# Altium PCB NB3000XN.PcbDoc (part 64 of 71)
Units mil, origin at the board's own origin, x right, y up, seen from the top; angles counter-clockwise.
Board outline 9527.56 x 6929.77 mil, 6 copper layers (Top Layer, GND+SHIELD, MidLayer1, MidLayer2, P2 - 3V3+5V0, Bottom Layer), stack 62.375 mil thick; 832 components, 1027 nets, 4655 pads, 4981 vias.
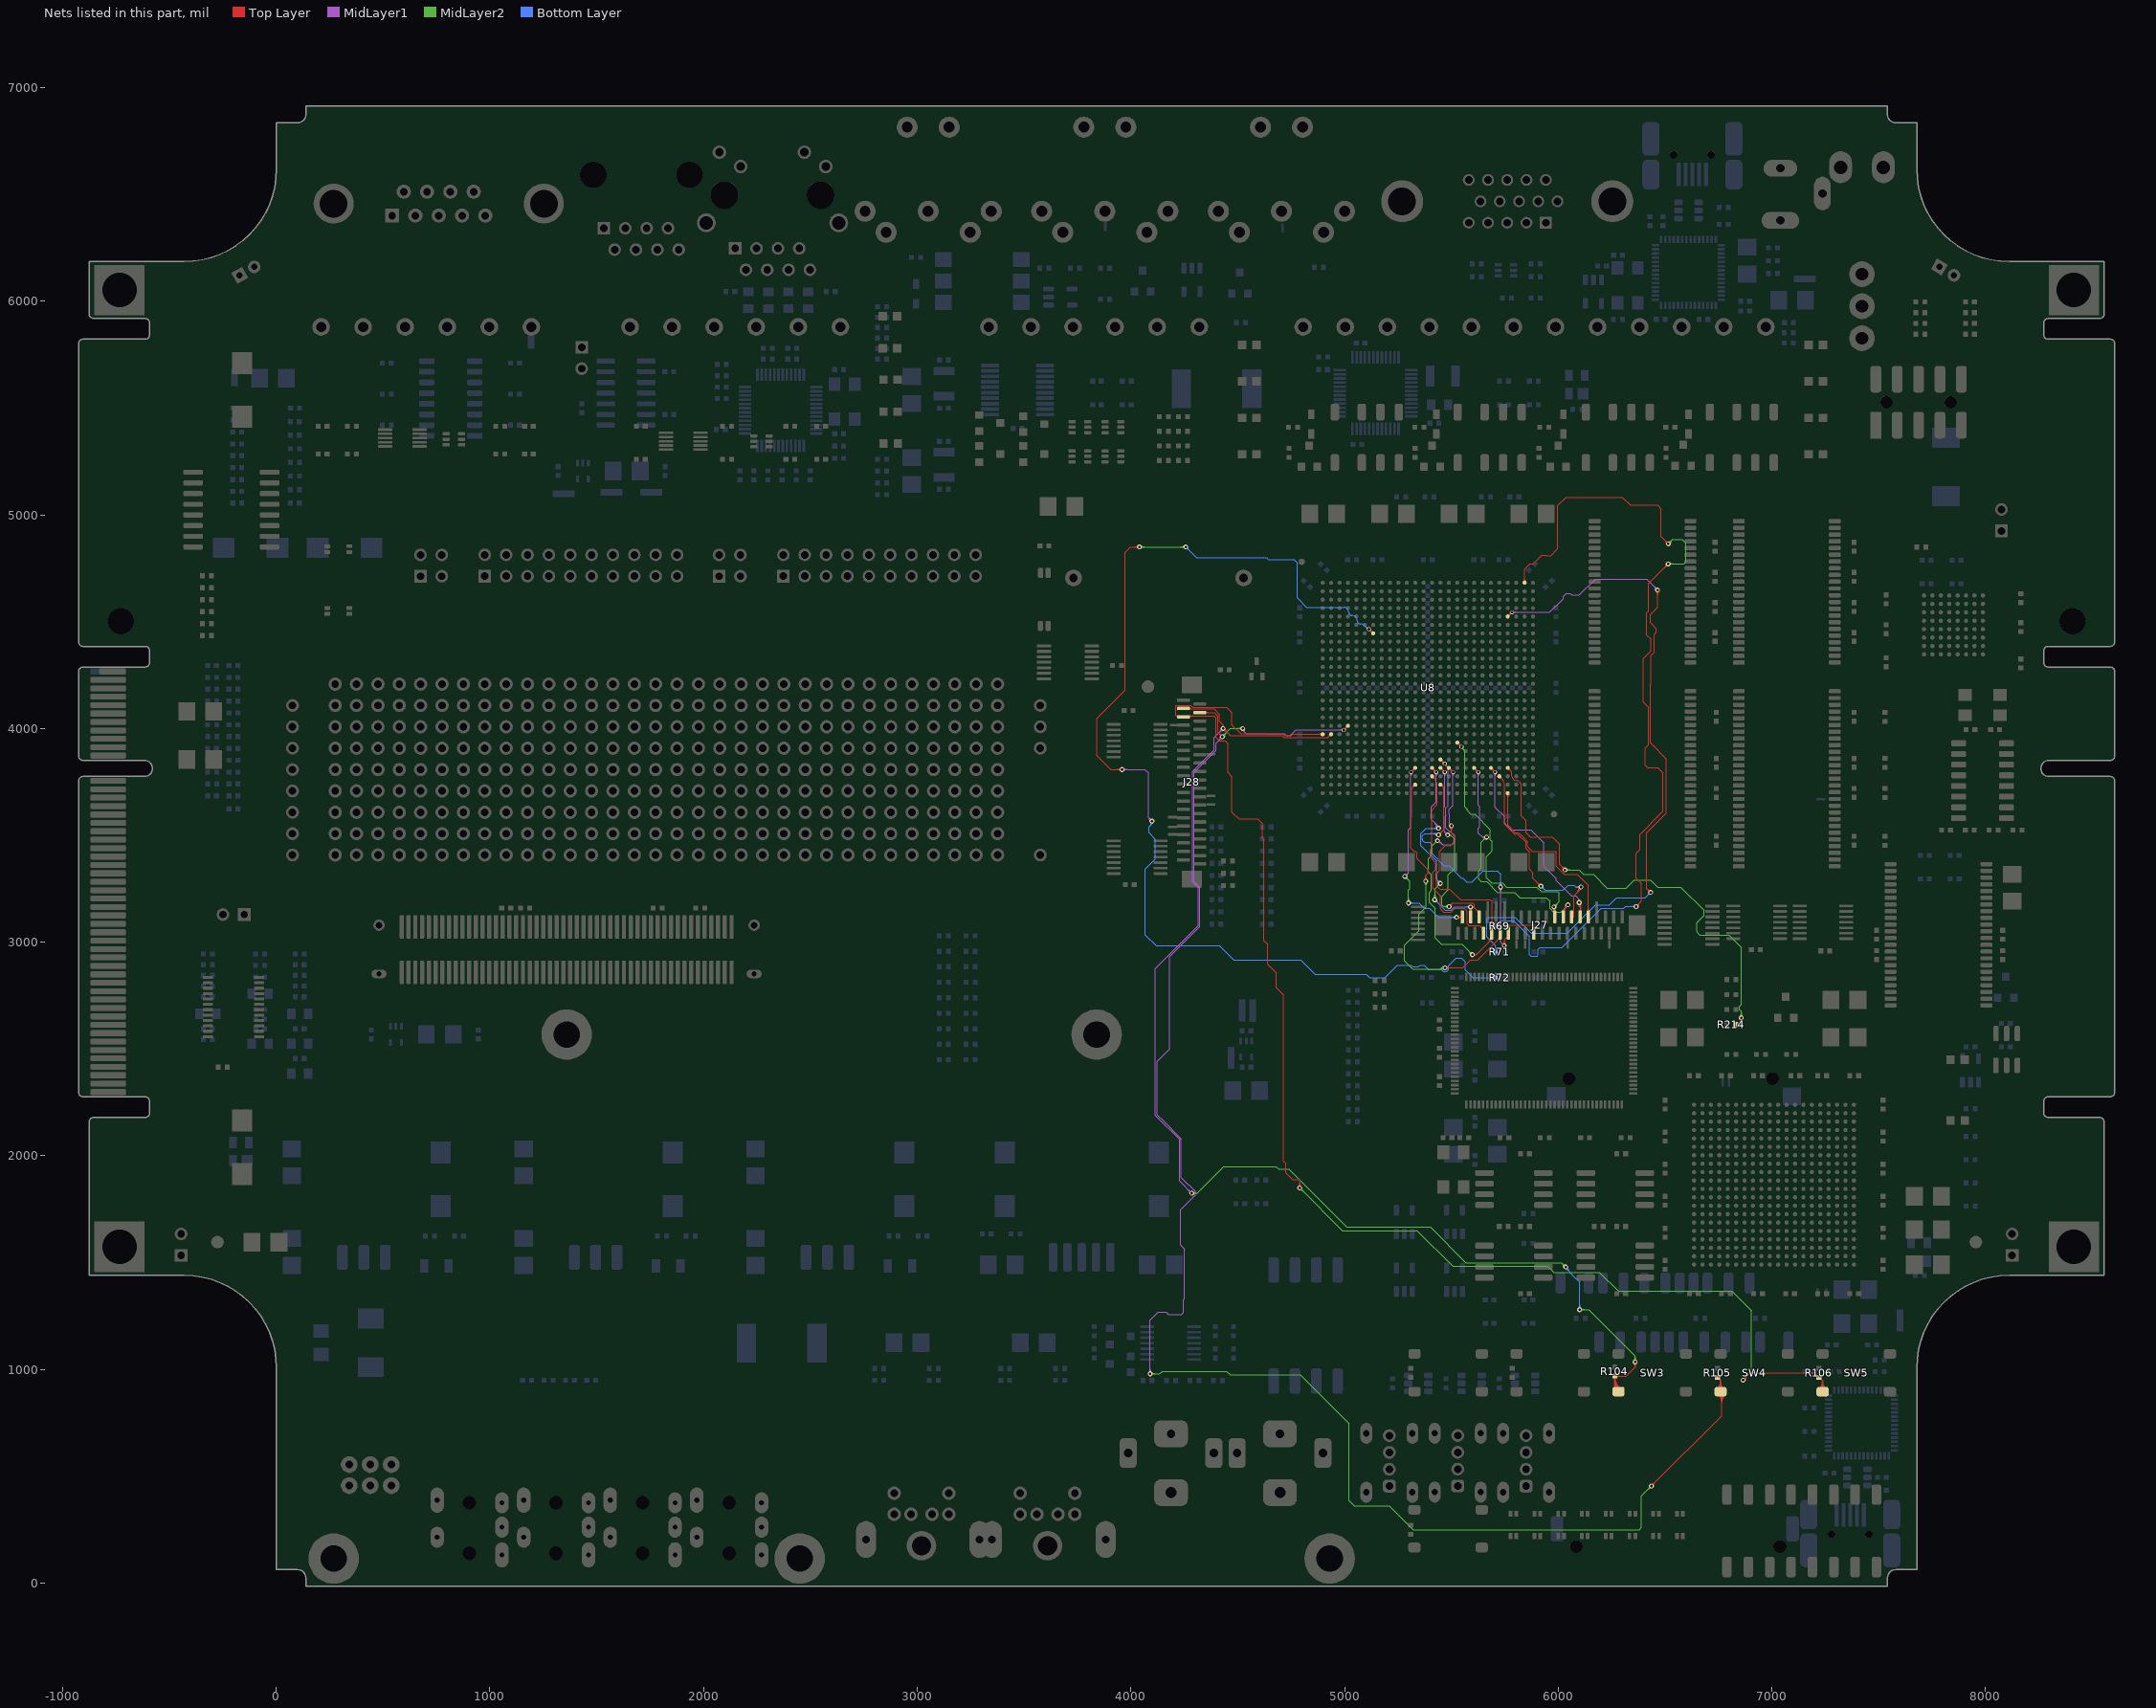
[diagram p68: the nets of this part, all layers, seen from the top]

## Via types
v1: diameter 23, hole 11.81, Top Layer to Bottom Layer, 3672 vias
v2: diameter 26, hole 11.81, Top Layer to Bottom Layer, 461 vias
v3: diameter 19, hole 11.81, Top Layer to Bottom Layer, tented both sides, 396 vias
v4: diameter 23.62, hole 11.81, Top Layer to Bottom Layer, 288 vias
v5: diameter 20, hole 11.81, Top Layer to Bottom Layer, 91 vias
v6: diameter 23, hole 11.81, Top Layer to Bottom Layer, tented both sides, 50 vias
v7: diameter 31, hole 11.81, Top Layer to Bottom Layer, 15 vias
v8: diameter 27.56, hole 11.81, Top Layer to Bottom Layer, tented both sides, 4 vias
v9: diameter 29, hole 11.81, Top Layer to Bottom Layer, 3 vias
v10: diameter 21, hole 11.81, Top Layer to Bottom Layer, 1 vias

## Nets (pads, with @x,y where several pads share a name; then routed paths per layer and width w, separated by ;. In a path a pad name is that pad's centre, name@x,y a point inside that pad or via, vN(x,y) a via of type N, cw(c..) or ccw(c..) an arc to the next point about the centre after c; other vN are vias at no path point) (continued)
SW#.D2: J28.3 R104.1 SW3.2 U8.W2 | length 7158.2
  Top Layer w4: J28.3@4246.61,4094.49 4248.52,4094.49 4251.3,4091.71 4390.19,4091.71 4415.19,4066.71 4415.19,4033.37 4431.86,4016.71 ; J28.3@4270.07,4095.81 ccw(c4279.98,4105.72) 4279.98,4091.71 ; J28.3@4272.89,4090.33 cw(c4276.21,4087.02) J28.3@4276.21,4091.71 ; J28.3@4272.89,4098.64 ccw(c4289.63,4115.38) 4289.63,4091.71 ; v1@4427.02,4008.22 ccw(c4421.99,4016.71) 4431.86,4016.71 ; v1@4431.86,3990.54 cw(c4431.86,3967.61) 4448.07,3983.82 cw(c4464.29,4000.04) v1@4441.36,4000.04 ; v1@4431.86,3994.54 cw(c4431.86,3981.26) 4441.25,3990.65 cw(c4450.64,4000.04) v1@4437.36,4000.04 ; v1@4436.7,4008.22 cw(c4441.73,4016.71) 4431.86,4016.71 ; U8.W2@4929.9,3973.46 cw(c4912.17,3973.46) 4924.71,3960.93 ; U8.W2@4937.24,3966.12 ccw(c4937.24,3948.4) 4924.71,3960.93 ; R104.1@6258.41,962.23 cw(c6242.5,946.32) 6265,946.32 cw(c6287.5,946.32) R104.1@6271.59,962.23 ; R104.1@6261.24,965.06 cw(c6252.16,955.98) 6265,955.98 cw(c6277.84,955.98) R104.1@6268.76,965.06 ; SW3.2@6262.02,911.31 ccw(c6254.84,918.49) SW3.2@6265,918.49 ; 6265,923.84 ccw(c6300.9,923.84) SW3.2@6276.85,897.18 ; 6265,932.83 ccw(c6309.01,932.83) SW3.2@6279.53,900.15 ; 6265,941.83 ccw(c6317.13,941.83) SW3.2@6282.21,903.12 ; 6265,950.82 ccw(c6325.24,950.82) SW3.2@6284.89,906.09 ; R104.1@6265,959.82 ccw(c6333.35,959.82) SW3.2@6287.57,909.06 ; R104.1@6269.25,965.06 cw(c6278.33,955.98) 6278.33,968.82 cw(c6278.33,981.66) R104.1@6269.25,972.58 ; R104.1@6272.08,962.23 cw(c6287.99,946.32) 6287.99,968.82 cw(c6287.99,991.32) R104.1@6272.08,975.41 ; SW3.2@6282.52,896.81 6265,914.33 R104.1@6265,968.82 ; SW3.2@6290.25,912.03 cw(c6341.47,968.81) R104.1@6265,968.82 ; v1@6353.19,1028.28 cw(c6336.97,1012.06) 6359.9,1012.06 cw(c6382.84,1012.06) v1@6366.62,1028.28 ; v1@6356.01,1031.11 cw(c6346.62,1021.72) 6359.9,1021.72 cw(c6373.18,1021.72) v1@6363.79,1031.11 ; v1(6359.9,1035) 6359.9,1010.93 6317.79,968.82 R104.1@6265,968.82 ; 4431.86,4016.71 v1(4431.86,4000.04) 4465.19,3966.71 4708.29,3966.71 4717.04,3957.96 ; 4717.04,3957.96 4796,3957.96 ; 4717.04,3957.96 4780,3957.96 4796,3957.96 ; 4796,3957.96 4855.26,3957.96 4860,3957.96 4870,3957.96 4917.53,3957.96 ccw(c4917.53,3968.11) 4924.71,3960.93
  MidLayer1 w4: v1@4275.5,1825 ccw(c4252.56,1825) 4268.78,1841.22 ccw(c4285,1857.43) v1@4285,1834.5 ; v1@4279.5,1825 ccw(c4266.22,1825) 4275.61,1834.39 ccw(c4285,1843.78) v1@4285,1830.5 ; v1(4285,1825) 4228,1882 4228,2076.69 4115.19,2189.5 4115.19,2877.67 4315.19,3077.67 4315.19,3255 4288.52,3281.67 4288.52,3798.71 4390.19,3900.37 4390.19,3958.37 v1(4431.86,4000.04) ; v1@4422.36,4000.04 cw(c4399.42,4000.04) 4415.64,3983.82 cw(c4431.86,3967.61) v1@4431.86,3990.54 ; v1@4426.36,4000.04 cw(c4413.08,4000.04) 4422.47,3990.65 cw(c4431.86,3981.26) v1@4431.86,3994.54
  MidLayer2 w4: v1@4285,1827.15 v1(4285,1825) 4310,1825 4435.04,1950.04 4678.29,1950.04 4691.15,1937.19 4739.36,1937.19 5009.84,1666.71 5401.5,1666.71 5568.17,1500.04 6014.96,1500.04 v4(6035,1480) ; v1@4288.89,1821.11 cw(c4298.28,1811.72) 4298.28,1825 cw(c4298.28,1838.28) v1@4288.89,1828.89 ; v1@4291.72,1818.28 cw(c4307.93,1802.06) 4307.93,1825 cw(c4307.93,1847.93) v1@4291.72,1831.72 ; v4@6025.19,1480 ccw(c6001.5,1480) 6018.25,1496.75 ccw(c6035,1513.5) v4@6035,1489.81 ; v4@6029.19,1480 ccw(c6015.16,1480) 6025.08,1489.92 ccw(c6035,1499.84) v4@6035,1485.81 ; v4(6100,1280) 6143.56,1280 6359.9,1063.66 v1(6359.9,1035) ; v4@6104.11,1275.89 cw(c6114.03,1265.97) 6114.03,1280 cw(c6114.03,1294.03) v4@6104.11,1284.11 ; v4@6106.94,1273.06 cw(c6123.69,1256.31) 6123.69,1280 cw(c6123.69,1303.69) v4@6106.94,1286.94 ; v1@6353.19,1041.72 ccw(c6336.97,1057.93) 6359.9,1057.93 ccw(c6382.84,1057.93) v1@6366.62,1041.72 ; v1@6356.01,1038.89 ccw(c6346.62,1048.28) 6359.9,1048.28 ccw(c6373.18,1048.28) v1@6363.79,1038.89
  Bottom Layer w4: v4@6035,1470.19 cw(c6035,1458.57) 6043.21,1466.79 ; v4(6035,1480) 6040,1480 6040,1470 6070,1440 ; v4@6036.81,1480 ccw(c6053.25,1480) 6041.63,1468.37 ; v4@6040.81,1480 ccw(c6066.91,1480) 6048.46,1461.54 ; v4@6044.81,1480 ccw(c6080.57,1480) 6055.28,1454.72 ; 6055,1455 6070,1440 ; v4@6093.06,1286.94 ccw(c6076.31,1303.69) 6100,1303.69 ccw(c6123.69,1303.69) v4@6106.94,1286.94 ; v4@6095.89,1284.11 ccw(c6085.97,1294.03) 6100,1294.03 ccw(c6114.03,1294.03) v4@6104.11,1284.11 ; v4(6100,1280) 6100,1410 6070,1440
SW#.D3: J28.4 R105.2 SW4.2 U8.V4 | length 9059.8
  Top Layer w4: J28.4@4331.86,4074.8 J28.4@4323.39,4074.8 4389.09,4074.8 4406.86,4057.04 4406.86,3983.37 v1(4428.52,3961.71) ; J28.4@4349.67,4070.65 cw(c4359.69,4060.62) 4359.69,4074.8 cw(c4359.69,4088.98) J28.4@4349.67,4078.96 ; v1@4419.02,3961.71 ccw(c4396.09,3961.71) 4412.31,3977.93 ccw(c4428.52,3994.14) v1@4428.52,3971.21 ; v1@4423.02,3961.71 ccw(c4409.75,3961.71) 4419.14,3971.1 ccw(c4428.52,3980.49) v1@4428.52,3967.21 ; v3(4996.3,3993.15) U8.V4@5015.98,4012.83 ; v3@5003.8,3993.15 cw(c5021.91,3993.15) 5009.1,4005.95 ; v3@5003.8,3993.15 cw(c5021.91,3993.15) 5009.1,4005.95 ; U8.V4@5008.48,4012.83 cw(c4990.38,4012.83) 5003.18,4000.03 cw(c5015.98,3987.23) U8.V4@5015.98,4005.33 ; U8.V4@5008.64,4012.83 cw(c4990.92,4012.83) 5003.45,4000.3 cw(c5015.98,3987.77) U8.V4@5015.98,4005.49 ; v1(6436.52,454.71) 6765.19,783.37 6765.19,891.25 SW4.2@6760.02,896.42 6760.02,948.8 R105.2@6745,963.82 ; v1@6436.52,460.21 ccw(c6436.52,473.49) 6445.91,464.1 ccw(c6455.3,454.71) v1@6442.02,454.71 ; v1@6436.52,464.21 ccw(c6436.52,487.14) 6452.74,470.93 ccw(c6468.96,454.71) v1@6446.02,454.71 ; SW4.2@6745.52,910.91 ccw(c6710.53,945.91) 6760.02,945.91 ccw(c6809.51,945.91) SW4.2@6774.52,910.91 ; R105.2@6745.69,958.5 cw(c6746.08,948.31) R105.2@6753.3,955.52 ; R105.2@6745.85,954.51 cw(c6746.56,935.83) 6759.77,949.05 cw(c6772.04,961.31) R105.2@6754.77,962.94 ; SW4.2@6748.35,908.08 ccw(c6720.19,936.25) 6760.02,936.25 ccw(c6799.85,936.25) SW4.2@6771.69,908.08 ; R105.2@6750.79,963.32 ccw(c6761.05,962.35) R105.2@6753.76,955.06 ; SW4.2@6751.18,905.26 ccw(c6729.84,926.59) 6760.02,926.59 ccw(c6790.2,926.59) SW4.2@6768.86,905.26 ; SW4.2@6751.52,881.92 cw(c6718.53,848.93) 6765.19,848.93 ; SW4.2@6754.35,884.75 cw(c6728.19,858.59) 6765.19,858.59 ; SW4.2@6757.18,887.58 cw(c6737.84,868.24) 6765.19,868.24 ; 6765.19,844.92 cw(c6817.51,844.92) SW4.2@6780.52,881.92 ; 6765.19,854.58 cw(c6807.86,854.58) SW4.2@6777.69,884.75 ; 6765.19,864.24 cw(c6798.2,864.24) SW4.2@6774.86,887.58 ; 6765.19,873.89 cw(c6788.54,873.89) SW4.2@6772.03,890.41 ; 5009.1,4005.95 cw(c4996.3,4018.76) 4996.3,4000.65 ccw(c4996.3,4018.76) 5009.1,4005.95
  MidLayer1 w4: v1@4083.28,986.72 ccw(c4067.06,1002.93) 4090,1002.93 ccw(c4112.93,1002.93) v1@4096.72,986.72 ; v1@4086.11,983.89 ccw(c4076.72,993.28) 4090,993.28 ccw(c4103.28,993.28) v1@4093.89,983.89 ; v1(4090,980) 4090,1230 4127.63,1267.63 4165,1267.63 4174.59,1258.04 4236.73,1258.04 4246,1267.31 4246,1327.31 4249.86,1331.17 4249.86,1565.02 4232.02,1582.85 4232.02,1747.28 4302.5,1817.75 4302.5,1832.25 4236,1898.75 4236,2080 4150,2166 4124.19,2191.81 4124.19,2442.98 4181.86,2500.65 4181.86,2933.02 4323.52,3074.69 4323.52,3257.98 4296.52,3284.98 4296.52,3795.39 4398.52,3897.39 4398.52,3931.71 v1(4428.52,3961.71) ; v1@4419.02,3961.71 cw(c4396.09,3961.71) 4412.31,3945.49 cw(c4428.52,3929.27) v1@4428.52,3952.21 ; v1@4423.02,3961.71 cw(c4409.75,3961.71) 4419.14,3952.32 cw(c4428.52,3942.93) v1@4428.52,3956.21 ; v1(4523.52,4000.04) 4523.52,3991.71 4540.19,3975.04 4718.52,3975.04 4726.86,3966.71 4746.06,3966.71 4772.5,3993.15 4860,3993.15 4870,3993.15 4918.62,3993.15 v3(4996.3,3993.15) ; v1@4524.92,3999.5 ccw(c4535.04,3995.55) 4527.36,3987.87 ; v1@4528.65,3998.04 ccw(c4541.28,3993.12) 4531.69,3983.54 ; v1@4532.38,3996.59 ccw(c4547.51,3990.69) 4536.02,3979.21 ; v3@4991,3987.85 ccw(c4978.19,3975.04) 4978.19,3993.15 ccw(c4978.19,4011.26) v3@4991,3998.45 ; v3@4991.11,3987.96 ccw(c4978.57,3975.42) 4978.57,3993.15 ccw(c4978.57,4010.88) v3@4991.11,3998.34
  MidLayer2 w4: v1(4090,980) 4135,980 4147.04,992.04 4447.96,992.04 4465,975 4793.69,975 5022,746.69 5022,386.11 5046.11,362 5208.94,362 5320.9,250.04 6200,250.04 ; v1@4093.89,976.11 cw(c4103.28,966.72) 4103.28,980 cw(c4103.28,993.28) v1@4093.89,983.89 ; v1@4096.72,973.28 cw(c4112.93,957.06) 4112.93,980 cw(c4112.93,1002.93) v1@4096.72,986.72 ; v1(4428.52,3961.71) 4466.86,4000.04 v1(4523.52,4000.04) ; v1@4428.52,3967.21 ccw(c4428.52,3980.49) 4437.91,3971.1 ccw(c4447.3,3961.71) v1@4434.02,3961.71 ; v1@4428.52,3971.21 ccw(c4428.52,3994.14) 4444.74,3977.93 ccw(c4460.96,3961.71) v1@4438.02,3961.71 ; v1@4516.81,3993.32 ccw(c4500.59,3977.11) 4500.59,4000.04 ccw(c4500.59,4022.98) v1@4516.81,4006.76 ; v1@4519.64,3996.15 ccw(c4510.25,3986.76) 4510.25,4000.04 ccw(c4510.25,4013.32) v1@4519.64,4003.93 ; 6200.33,249.71 6379.71,249.71 6390,260 6390,408.18 v1(6436.52,454.71) ; v1@6427.02,454.71 cw(c6404.09,454.71) 6420.31,438.49 cw(c6436.52,422.27) v1@6436.52,445.21 ; v1@6431.02,454.71 cw(c6417.75,454.71) 6427.14,445.32 cw(c6436.52,435.93) v1@6436.52,449.21
SW#.D4: J28.5 R106.1 SW5.2 U8.W1 | length 7278.1
  Top Layer w4: J28.5@4218.88,4053.38 ccw(c4216.52,4052.66) 4216.52,4055.12 ; J28.5@4218.88,4056.85 cw(c4216.52,4057.58) 4216.52,4055.12 ; J28.5@4270.07,4053.79 cw(c4281.13,4042.73) 4281.13,4058.37 ; J28.5@4272.89,4050.96 cw(c4290.78,4033.08) 4290.78,4058.37 ; v1@4783.47,1856.76 ccw(c4767.26,1872.98) 4790.19,1872.98 ccw(c4813.13,1872.98) v1@4796.91,1856.76 ; v1@4786.3,1853.93 ccw(c4776.91,1863.32) 4790.19,1863.32 ccw(c4803.47,1863.32) v1@4794.08,1853.93 ; v1(4790.19,1850.04) 4790.19,1885 4785.19,1890 4756.21,1890 4725,1921.21 4725,1965.03 4715.19,1974.84 4715.19,2753.02 4681.86,2786.35 4681.86,2855.39 4640.19,2897.06 4640.19,2989.81 4623.52,3006.48 4623.52,3478.02 4615.19,3486.36 4615.19,3555 4593.48,3576.71 4506.76,3576.71 4473.52,3609.94 4473.52,3775.65 4453.86,3795.32 4453.86,3928.04 4440.19,3941.71 4415.19,3941.71 4398.52,3958.37 4398.52,4050.04 4390.19,4058.37 4261.37,4058.37 J28.5@4256.86,4053.86 ; U8.W1@4892.57,3968.16 ccw(c4879.77,3955.36) 4879.77,3973.46 ccw(c4879.77,3991.57) U8.W1@4892.57,3978.77 ; U8.W1@4892.68,3968.27 ccw(c4880.15,3955.74) 4880.15,3973.46 ccw(c4880.15,3991.19) U8.W1@4892.68,3978.66 ; U8.W1@4897.87,3973.46 4870,3973.46 4860,3973.46 4756.76,3973.46 4750,3966.71 4719.61,3966.71 4711.31,3975 4635,3975 4515.19,3975.04 4473.52,4016.71 4473.52,4075.04 4448.52,4100.04 4288.86,4100.04 4280.52,4108.37 4213.52,4108.37 4210.52,4105.37 4210.52,4061.12 4216.52,4055.12 ; v1(6865.19,950.04) 6900.15,985 7198.82,985 R106.1@7220,963.82 ; v1@6865.19,955.54 ccw(c6865.19,968.82) 6874.58,959.43 ccw(c6883.97,950.04) v1@6870.69,950.04 ; v1@6865.19,959.54 ccw(c6865.19,982.48) 6881.41,966.26 ccw(c6897.63,950.04) v1@6874.69,950.04 ; 7203.25,980.57 cw(c7186.5,963.82) R106.1@7210.19,963.82 ; 7204.44,979.38 ccw(c7219.51,994.45) R106.1@7219.51,973.14 ; R106.1@7210.08,973.74 cw(c7200.16,963.82) R106.1@7214.19,963.82 ; R106.1@7211.27,972.55 ccw(c7219.51,980.79) R106.1@7219.51,969.14 ; R106.1@7215.19,963.82 R106.1@7220,963.82 ; R106.1@7220.49,954.5 cw(c7220.49,933.19) 7235.56,948.26 ; R106.1@7220.49,958.5 cw(c7220.49,946.85) R106.1@7228.73,955.09 ; SW5.2@7223.02,910.91 ccw(c7188.03,945.91) 7237.52,945.91 ccw(c7287.01,945.91) SW5.2@7252.02,910.91 ; R106.1@7225.81,963.82 ccw(c7239.84,963.82) R106.1@7229.92,953.9 ; SW5.2@7225.85,908.08 ccw(c7197.69,936.25) 7237.52,936.25 ccw(c7277.35,936.25) SW5.2@7249.19,908.08 ; SW5.2@7228.68,905.26 ccw(c7207.34,926.59) 7237.52,926.59 ccw(c7267.7,926.59) SW5.2@7246.36,905.26 ; R106.1@7229.81,963.82 ccw(c7253.5,963.82) 7236.75,947.07 ; SW5.2@7237.52,915 SW5.2@7237.52,896.42 7237.52,946.3 R106.1@7220,963.82 ; 4216.52,4055.12 J28.5@4246.61,4055.12 J28.5@4251.78,4055.12 ; J28.5@4251.78,4055.12 4256.86,4055.12 J28.5@4256.86,4053.86 ; J28.5@4251.78,4055.12 J28.5@4256.86,4050.04 ; J28.5@4256.86,4050.04 4255.04,4051.86 4255.04,4052.04 J28.5@4256.86,4053.86 ; J28.5@4256.86,4050.04 J28.5@4256.86,4053.86
  MidLayer2 w4: v1@4790.19,1840.54 cw(c4790.19,1817.61) 4806.41,1833.82 cw(c4822.63,1850.04) v1@4799.69,1850.04 ; v1@4790.19,1844.54 cw(c4790.19,1831.26) 4799.58,1840.65 cw(c4808.97,1850.04) v1@4795.69,1850.04 ; v1(4790.19,1850.04) 4990.19,1650.04 5340.19,1650.04 5506.86,1483.37 5951.63,1483.37 5980,1455 6193.56,1455 6281.52,1367.04 6812.96,1367.04 6905,1275 6905,989.85 v1(6865.19,950.04) ; v1@6865.19,955.54 ccw(c6865.19,968.82) 6874.58,959.43 ccw(c6883.97,950.04) v1@6870.69,950.04 ; v1@6865.19,959.54 ccw(c6865.19,982.48) 6881.41,966.26 ccw(c6897.63,950.04) v1@6874.69,950.04
TCK: R69.2 U8.A25 | length 4610.3
  Top Layer w4: U8.A25@5837.45,4687.43 ccw(c5824.65,4700.23) 5842.76,4700.23 ccw(c5860.86,4700.23) U8.A25@5848.06,4687.43 ; U8.A25@5837.56,4687.32 ccw(c5825.03,4699.85) 5842.76,4699.85 ccw(c5860.48,4699.85) U8.A25@5847.95,4687.32 ; U8.A25@5842.76,4682.13 5842.76,4710 5842.76,4720 5842.76,4746.65 5867.65,4771.54 5882.75,4771.54 5923.21,4812 5941.94,4812 5944.44,4809.5 5965.56,4809.5 5998.52,4842.46 5998.52,5044.71 6037.19,5083.37 6300.19,5083.37 6337.52,5046.04 6465.19,5046.04 6481.86,5029.37 6481.86,4898.37 v1(6515.52,4864.71) ; v1(6365.19,3166.71) 6390.19,3191.71 6390.19,3275.04 6365.19,3300.04 6365.19,3416.71 6381.86,3433.37 6381.86,3504.37 6490.19,3612.71 6490.19,3791.71 6465.19,3816.71 6418.86,3816.71 6406.86,3828.71 6406.86,3908.37 6423.52,3925.04 6423.52,4098.71 6398.52,4123.71 6398.52,4328.34 6433.52,4363.34 6433.52,4420.04 6415.19,4438.37 6415.19,4541.71 6423.52,4550.04 6423.52,4678.71 v1(6515.19,4770.37) ; v1@6365.19,3172.21 ccw(c6365.19,3185.49) 6374.58,3176.1 ccw(c6383.97,3166.71) v1@6370.69,3166.71 ; v1@6365.19,3176.21 ccw(c6365.19,3199.14) 6381.41,3182.93 ccw(c6397.63,3166.71) v1@6374.69,3166.71 ; v1@6505.69,4770.37 cw(c6482.76,4770.37) 6498.97,4754.16 cw(c6515.19,4737.94) v1@6515.19,4760.87 ; v1@6506.02,4864.71 ccw(c6483.09,4864.71) 6499.31,4880.93 ccw(c6515.52,4897.14) v1@6515.52,4874.21 ; v1@6509.69,4770.37 cw(c6496.41,4770.37) 6505.8,4760.99 cw(c6515.19,4751.6) v1@6515.19,4764.87 ; v1@6510.02,4864.71 ccw(c6496.75,4864.71) 6506.14,4874.1 ccw(c6515.52,4883.49) v1@6515.52,4870.21
  MidLayer2 w4: v1(6515.19,4770.37) 6588.52,4770.37 6598.52,4780.37 6598.52,4866.71 6580.52,4884.71 6535.52,4884.71 v1(6515.52,4864.71) ; v1@6515.52,4870.21 ccw(c6515.52,4883.49) 6524.91,4874.1 ccw(c6534.3,4864.71) v1@6521.02,4864.71 ; v1@6515.52,4874.21 ccw(c6515.52,4897.14) 6531.74,4880.93 ccw(c6547.96,4864.71) v1@6525.02,4864.71 ; v1@6519.08,4766.49 cw(c6528.47,4757.1) 6528.47,4770.37 cw(c6528.47,4783.65) v1@6519.08,4774.26 ; v1@6521.91,4763.66 cw(c6538.13,4747.44) 6538.13,4770.37 cw(c6538.13,4793.31) v1@6521.91,4777.09
  Bottom Layer w4: R69.2@5705.82,3075 5731.19,3100.37 5792.23,3100.37 5865,3027.6 5865,2941.9 5872.52,2934.37 5902.52,2934.37 5906.86,2938.71 5906.86,2966.71 5915.19,2975.04 6017.86,2975.04 6201.19,3158.37 6306.86,3158.37 6315.19,3166.71 v1(6365.19,3166.71) ; R69.2@5705.82,3080.81 ccw(c5705.82,3094.84) R69.2@5715.74,3084.92 ; R69.2@5705.82,3084.81 ccw(c5705.82,3108.5) 5722.57,3091.75 ; R69.2@5711.14,3075.49 cw(c5722.79,3075.49) R69.2@5714.55,3083.73 ; R69.2@5715.14,3075.49 cw(c5736.45,3075.49) 5721.38,3090.56 ; v1@6358.47,3159.99 ccw(c6342.26,3143.77) 6342.26,3166.71 ccw(c6342.26,3189.64) v1@6358.47,3173.43 ; v1@6361.3,3162.82 ccw(c6351.91,3153.43) 6351.91,3166.71 ccw(c6351.91,3179.99) v1@6361.3,3170.6
TDI: R72.2 U8.G7 | length 6027.5
  Top Layer w4: v1@3952.14,3801.66 ccw(c3935.92,3785.44) 3935.92,3808.37 ccw(c3935.92,3831.31) v1@3952.14,3815.09 ; v1@3954.97,3804.49 ccw(c3945.58,3795.1) 3945.58,3808.37 ccw(c3945.58,3821.65) v1@3954.97,3812.26 ; v1(3958.86,3808.37) 3905.52,3808.37 3840.19,3873.71 3840.19,4046.69 3973.52,4180.02 3973.52,4825.04 3998.52,4850.04 v1(4040.19,4850.04) ; v1@4033.47,4843.32 ccw(c4017.26,4827.11) 4017.26,4850.04 ccw(c4017.26,4872.98) v1@4033.47,4856.76 ; v1@4036.3,4846.15 ccw(c4026.91,4836.76) 4026.91,4850.04 ccw(c4026.91,4863.32) v1@4036.3,4853.93 ; v3(5114.41,4465.59) U8.G7@5134.09,4445.91 ; U8.G7@5126.59,4445.91 ccw(c5108.49,4445.91) 5121.29,4458.71 ccw(c5134.09,4471.51) U8.G7@5134.09,4453.41 ; U8.G7@5126.75,4445.91 ccw(c5109.03,4445.91) 5121.56,4458.44 ccw(c5134.09,4470.97) U8.G7@5134.09,4453.25 ; 5127.21,4452.79 ccw(c5114.41,4439.98) 5114.41,4458.09 cw(c5114.41,4439.98) 5127.21,4452.79 ; 5127.21,4452.79 cw(c5140.02,4465.59) 5121.91,4465.59 ccw(c5140.02,4465.59) 5127.21,4452.79
  MidLayer1 w4: v1(3958.86,3808.37) 4065.19,3808.37 4081.86,3791.71 4081.86,3583.37 v1(4098.52,3566.71) ; v1@3962.75,3804.49 cw(c3972.14,3795.1) 3972.14,3808.37 cw(c3972.14,3821.65) v1@3962.75,3812.26 ; v1@3965.57,3801.66 cw(c3981.79,3785.44) 3981.79,3808.37 cw(c3981.79,3831.31) v1@3965.57,3815.09 ; v1@4089.02,3566.71 ccw(c4066.09,3566.71) 4082.31,3582.93 ccw(c4098.52,3599.14) v1@4098.52,3576.21 ; v1@4093.02,3566.71 ccw(c4079.75,3566.71) 4089.14,3576.1 ccw(c4098.52,3585.49) v1@4098.52,3572.21
  MidLayer2 w4: v1(4040.19,4850.04) v1(4256.86,4850.04) ; v1@4044.08,4846.15 cw(c4053.47,4836.76) 4053.47,4850.04 cw(c4053.47,4863.32) v1@4044.08,4853.93 ; v1@4046.91,4843.32 cw(c4063.13,4827.11) 4063.13,4850.04 cw(c4063.13,4872.98) v1@4046.91,4856.76 ; v1@4250.14,4843.32 ccw(c4233.92,4827.11) 4233.92,4850.04 ccw(c4233.92,4872.98) v1@4250.14,4856.76 ; v1@4252.97,4846.15 ccw(c4243.58,4836.76) 4243.58,4850.04 ccw(c4243.58,4863.32) v1@4252.97,4853.93
  Bottom Layer w4: 4091.59,3546.59 ccw(c4084.78,3553.4) v1@4091.7,3560.1 ; 4094.47,3549.47 ccw(c4087.7,3556.23) v1@4094.57,3562.88 ; 4097.34,3552.34 ccw(c4090.62,3559.06) v1@4097.45,3565.66 ; v1(4098.52,3566.71) 4098.52,3553.52 4085,3540 4085,3511.56 4115.19,3481.37 4115.19,3388.71 4068.19,3341.71 4068.19,3033.35 4118.5,2983.04 4415.17,2983.04 4481.17,2917.04 4788,2917.04 4795.21,2917.04 4862.21,2850.04 5100.84,2850.04 5117.84,2833.04 5188.19,2833.04 5248.52,2893.37 5311.15,2893.37 5318.98,2885.54 5346.73,2885.54 5354.57,2893.37 5371.86,2893.37 5391.19,2874.04 5392.73,2872.5 5452.75,2872.5 5462.75,2862.5 5477.25,2862.5 5487.5,2872.75 5487.5,2889.02 5523.52,2925.04 5548.52,2925.04 5565.19,2908.37 5565.19,2870.73 5600.92,2835 R72.2@5705.82,2835 ; 4100.21,3555.21 ccw(c4093.54,3561.88) v1@4100.32,3568.45 ; v1@4256.86,4840.54 cw(c4256.86,4817.61) 4273.07,4833.82 cw(c4289.29,4850.04) v1@4266.36,4850.04 ; v1@4256.86,4844.54 cw(c4256.86,4831.26) 4266.25,4840.65 cw(c4275.64,4850.04) v1@4262.36,4850.04 ; v1(4256.86,4850.04) 4298.52,4808.37 4307.19,4799.71 4635.17,4799.71 4643.17,4791.71 4764,4791.71 4779,4776.71 4779,4611 4821.9,4568.1 4860,4568.1 4870,4568.1 4996.3,4568.1 cw(c4996.3,4544.33) 5020.07,4544.33 ccw(c5035.67,4544.33) 5035.67,4528.73 cw(c5035.67,4504.96) 5059.44,4504.96 ccw(c5075.04,4504.96) 5075.04,4489.36 cw(c5075.04,4465.59) 5091.85,4482.4 5099.58,4475.98 ; v3@5107.02,4464.29 ccw(c5089.19,4461.14) 5099.58,4475.98 ; v3@5113.11,4472.98 cw(c5109.96,4490.81) 5099.58,4475.98 ; R72.2@5699.23,2828.41 ccw(c5683.32,2812.5) 5683.32,2835 ccw(c5683.32,2857.5) R72.2@5699.23,2841.59 ; R72.2@5702.06,2831.24 ccw(c5692.98,2822.16) 5692.98,2835 ccw(c5692.98,2847.84) R72.2@5702.06,2838.76 ; R72.2@5705.82,2835 5705.82,2834.51 R72.2@5705.82,2835
TDO: R71.2 U8.E23 | length 3869.6
  Top Layer w4: U8.E23@5764.02,4524.65 v3(5783.7,4544.33) ; U8.E23@5764.02,4531.99 ccw(c5764.02,4549.71) 5776.55,4537.18 ccw(c5789.08,4524.65) U8.E23@5771.36,4524.65 ; U8.E23@5764.02,4532.15 ccw(c5764.02,4550.25) 5776.82,4537.45 ccw(c5789.62,4524.65) U8.E23@5771.52,4524.65 ; v1@6423.69,3233.37 ccw(c6400.76,3233.37) 6416.97,3249.59 ccw(c6433.19,3265.81) v1@6433.19,3242.87 ; v1@6427.69,3233.37 ccw(c6414.41,3233.37) 6423.8,3242.76 ccw(c6433.19,3252.15) v1@6433.19,3238.87 ; v1(6433.19,3233.37) 6415.19,3251.37 6415.19,3513.39 6506.86,3605.06 6506.86,3858.37 6431.86,3933.37 6431.86,4206.37 6433.86,4208.37 6433.86,4341.04 6449.52,4356.71 6449.52,4440 6459.52,4450 6459.52,4467.04 6431.86,4494.71 6431.86,4533.39 6465.19,4566.73 v1(6465.19,4648.71) ; v1@6458.47,4641.99 cw(c6442.26,4625.77) 6465.19,4625.77 cw(c6488.13,4625.77) v1@6471.91,4641.99 ; v1@6461.3,4644.82 cw(c6451.91,4635.43) 6465.19,4635.43 cw(c6478.47,4635.43) v1@6469.08,4644.82 ; 5770.9,4531.53 cw(c5783.7,4518.72) 5783.7,4536.83 ccw(c5783.7,4518.72) 5770.9,4531.53 ; 5770.9,4531.53 ccw(c5758.09,4544.33) 5776.2,4544.33 cw(c5758.09,4544.33) 5770.9,4531.53
  MidLayer1 w4: v3(5783.7,4544.33) 5861.38,4544.33 5910,4544.33 5920,4544.33 5924.74,4544.33 5959.48,4544.33 6023.52,4608.37 6023.52,4618.71 6038.19,4633.37 6056.86,4633.37 6065.19,4625.04 6098.52,4625.04 6173.52,4700.04 6413.86,4700.04 v1(6465.19,4648.71) ; v3@5788.89,4539.14 cw(c5801.43,4526.6) 5801.43,4544.33 cw(c5801.43,4562.06) v3@5788.89,4549.52 ; v1@6455.69,4648.71 ccw(c6432.76,4648.71) 6448.97,4664.93 ccw(c6465.19,4681.14) v1@6465.19,4658.21 ; v1@6459.69,4648.71 ccw(c6446.41,4648.71) 6455.8,4658.1 ccw(c6465.19,4667.49) v1@6465.19,4654.21 ; 5801.81,4544.33 cw(c5801.81,4562.44) 5789,4549.63 ccw(c5801.81,4562.44) 5801.81,4544.33 ; 5801.81,4544.33 ccw(c5801.81,4526.22) 5789,4539.03 cw(c5801.81,4526.22) 5801.81,4544.33
  Bottom Layer w4: R71.2@5699.23,2962.08 ccw(c5683.32,2977.99) 5705.82,2977.99 ccw(c5728.32,2977.99) R71.2@5712.41,2962.08 ; R71.2@5702.06,2959.25 ccw(c5692.98,2968.33) 5705.82,2968.33 ccw(c5718.66,2968.33) R71.2@5709.58,2959.25 ; R71.2@5705.82,2955 5705.82,2984.41 5665.19,3025.04 5665.19,3108.37 5673.52,3116.71 5798.52,3116.71 5873.52,3041.71 6041.88,3041.71 6175.17,3175 6225,3175 6240.19,3175.04 6273.52,3208.37 6408.19,3208.37 v1(6433.19,3233.37) ; v1@6423.69,3233.37 cw(c6400.76,3233.37) 6416.97,3217.16 cw(c6433.19,3200.94) v1@6433.19,3223.87 ; v1@6427.69,3233.37 cw(c6414.41,3233.37) 6423.8,3223.99 cw(c6433.19,3214.6) v1@6433.19,3227.87
TFT_IO.BL: R214.2 U8.AC23 | length 2455.9
  Top Layer w4: v1@6022.36,3338.71 ccw(c5999.42,3338.71) 6015.64,3354.93 ccw(c6031.86,3371.14) v1@6031.86,3348.21 ; v1@6026.36,3338.71 ccw(c6013.08,3338.71) 6022.47,3348.1 ccw(c6031.86,3357.49) v1@6031.86,3344.21 ; v1(6031.86,3338.71) 6006.86,3363.71 6006.86,3458.37 5973.52,3491.71 5917,3491.71 5873.29,3491.71 5869.84,3491.71 5849.02,3512.52 5849.02,3515.98 5849.02,3530 5849.02,3568.94 5827.25,3590.71 5827.25,3660 5827.25,3670 5827.25,3736.73 ccw(c5817.1,3736.73) 5824.28,3743.91 5824.27,3744.13 5816.36,3752.05 ccw(c5803.39,3737.24) 5803.39,3756.93 cw(c5803.39,3776.62) 5783.7,3776.61 5783.7,3788.06 ccw(c5764.02,3788.06) 5777.94,3801.97 5777.94,3802.06 5776.55,3803.45 ; R214.2@6831.18,2615 6831.18,2616.71 6848.52,2616.71 ; R214.2@6838.33,2621.47 ccw(c6848.52,2630) 6848.52,2616.71 ; R214.2@6839.45,2611.2 cw(c6848.52,2606.48) 6848.52,2616.71 ; v1@6850.67,2638.5 cw(c6839.13,2625.04) 6856.86,2625.04 ; v1@6853.28,2641.53 cw(c6846.59,2633.74) 6856.86,2633.74 cw(c6867.12,2633.74) v1@6860.44,2641.53 ; v1(6856.86,2645.71) 6856.86,2625.04 ; v1@6863.04,2638.5 ccw(c6874.58,2625.04) 6856.86,2625.04 ; 5776.55,3803.45 cw(c5789.08,3815.98) 5771.36,3815.98 ccw(c5789.08,3815.98) 5776.55,3803.45 ; 5776.55,3803.45 ccw(c5764.02,3790.92) 5764.02,3808.64 cw(c5764.02,3790.92) 5776.55,3803.45 ; 6848.52,2616.71 6856.86,2625.04
  MidLayer2 w4: v1@6031.86,3330.37 v1(6031.86,3338.71) 6097.54,3338.71 6119.54,3316.71 6166.19,3316.71 6229.1,3253.8 6318.95,3253.8 6356.86,3291.71 6431.86,3291.71 6465.19,3258.37 6573.52,3258.37 6681.86,3150.04 6681.86,3125.04 6648.52,3091.71 6648.52,3048.37 ; v1@6035.75,3334.82 cw(c6045.14,3325.43) 6045.14,3338.71 cw(c6045.14,3351.99) v1@6035.75,3342.6 ; v1@6038.57,3331.99 cw(c6054.79,3315.77) 6054.79,3338.71 cw(c6054.79,3361.64) v1@6038.57,3345.43 ; v1@6850.14,2652.43 ccw(c6833.92,2668.64) 6856.86,2668.64 ccw(c6879.79,2668.64) v1@6863.57,2652.43 ; v1@6852.97,2649.6 ccw(c6843.58,2658.99) 6856.86,2658.99 ccw(c6870.14,2658.99) v1@6860.75,2649.6 ; v1(6856.86,2645.71) 6856.86,2676.67 6848.52,2685 6848.52,2700.04 6856.86,2708.37 6856.86,2975.04 6798.52,3033.37 6663.52,3033.37 6656.86,3040.04 ; 6648.52,3048.37 6656.86,3040.04 ; 6648.52,3048.37 6656.86,3040.04
TFT_IO.CS: J27.22 U8.AC16 | length 1507.4
  Top Layer w4: U8.AC16@5488.43,3808.48 cw(c5488.43,3790.38) 5501.23,3803.18 cw(c5514.03,3815.98) U8.AC16@5495.93,3815.98 ; U8.AC16@5488.43,3808.64 cw(c5488.43,3790.92) 5500.96,3803.45 cw(c5513.49,3815.98) U8.AC16@5495.77,3815.98 ; U8.AC16@5488.43,3815.98 v3(5508.11,3796.3) ; v1@5493.28,3538.28 cw(c5476.7,3521.7) 5500.15,3521.7 ; v1@5496.11,3541.11 cw(c5486.36,3531.36) 5500.15,3531.36 ; v1(5500,3545) 5500.15,3545 5500.15,3511.87 5512.02,3500 5512.02,3467.79 5496.11,3451.87 5471.87,3451.87 5444.31,3424.31 5444.31,3335.33 5431.02,3322.04 5431.02,3263.98 5445.91,3249.09 5492.39,3249.09 5542.28,3199.21 5682.69,3199.21 5690.19,3191.71 5690.19,3089.04 5698.52,3080.71 5876.19,3080.71 5890.19,3066.71 5890.19,3063.73 5885.9,3063.73 J27.22@5885.89,3041.61 ; 5500.15,3522.43 cw(c5522.57,3522.43) v1@5506.72,3538.28 ; 5500.15,3532.08 cw(c5512.92,3532.08) v1@5503.89,3541.11 ; 5878.72,3078.18 cw(c5865.8,3065.25) J27.22@5884.02,3063.88 ; 5884.88,3072.01 cw(c5877.26,3064.39) J27.22@5888.01,3063.58 ; 5495.31,3809.1 cw(c5482.5,3796.3) 5500.61,3796.3 ccw(c5482.5,3796.3) 5495.31,3809.1 ; 5495.31,3809.1 ccw(c5508.11,3821.91) 5508.11,3803.8 cw(c5508.11,3821.91) 5495.31,3809.1
  MidLayer1 w4: 5489.5,3599.44 5489.5,3599.88 ; v1(5500,3545) 5500.15,3545 5490.5,3554.65 5490.5,3598.88 5489.5,3599.88 ; v3@5502.81,3791 cw(c5490,3778.19) 5508.11,3778.19 cw(c5526.22,3778.19) v3@5513.41,3791 ; v3@5502.92,3791.11 cw(c5490.38,3778.57) 5508.11,3778.57 cw(c5525.84,3778.57) v3@5513.3,3791.11 ; v3(5508.11,3796.3) 5508.11,3718.62 5508.11,3670 5508.11,3660 5508.11,3640.27 5489.5,3621.66 5489.5,3599.88
TFT_IO.DB0: J27.34 U8.AD14 | length 1037.3
  Top Layer w4: 5407.69,3454.96 5407.69,3440.46 5402,3434.77 5402,3398 5427.5,3372.5 5427.5,3360 5427.5,3346.6 5427.5,3341.14 5414,3327.64 5414,3320 5414,3252.21 5448.52,3217.69 5448.52,3156.37 5463.19,3141.71 5498.52,3141.71 5515.19,3158.37 5561.52,3158.37 5573.52,3146.37 5573.52,3086.04 5581.86,3077.71 5631.86,3077.71 5648.52,3061.04 5648.52,3050.04 5649.67,3050.04 J27.34@5649.67,3041.61 ; 5407.7,3440.47 5407.7,3618.89 5433.55,3644.73 5433.55,3660 5433.55,3670 5433.55,3736.73 ccw(c5394.87,3736.73) 5422.22,3764.08 ; U8.AD14@5409.69,3769.27 cw(c5409.69,3751.55) 5422.22,3764.08 ; U8.AD14@5417.03,3776.61 ccw(c5434.75,3776.61) 5422.22,3764.08 ; 5633.78,3075.78 ccw(c5648.72,3090.72) J27.34@5649.46,3069.61 ; 5640.28,3069.28 ccw(c5649.16,3078.16) J27.34@5649.6,3065.61 ; J27.34@5642.36,3067.2 cw(c5638.9,3063.74) J27.34@5643.8,3063.74
TFT_IO.DB1: J27.32 U8.AB15 | length 1707.5
  Top Layer w4: U8.AB15@5449.06,3847.85 cw(c5449.06,3829.75) 5461.86,3842.55 cw(c5474.66,3855.35) U8.AB15@5456.56,3855.35 ; U8.AB15@5449.06,3848.01 cw(c5449.06,3830.29) 5461.59,3842.82 cw(c5474.12,3855.35) U8.AB15@5456.4,3855.35 ; U8.AB15@5449.06,3855.35 v3(5468.74,3835.67) ; v1(5598.52,2941.71) 5616.19,2941.71 ; v1@5606.45,2936.47 cw(c5616.19,2930.03) 5616.19,2941.71 ; v1@5606.45,2946.95 ccw(c5616.19,2953.38) 5616.19,2941.71 ; 5675.53,3001.05 ccw(c5657.09,3019.49) J27.32@5683.17,3019.49 ; 5682.36,3007.87 ccw(c5670.74,3019.49) J27.32@5687.17,3019.49 ; J27.32@5689.04,3041.61 5689.04,3019.48 5689.04,3016.71 5689.19,3016.71 5690.19,3015.71 5616.19,2941.71 ; 5455.94,3848.47 cw(c5443.13,3835.67) 5461.24,3835.67 ccw(c5443.13,3835.67) 5455.94,3848.47 ; 5455.94,3848.47 ccw(c5468.74,3861.28) 5468.74,3843.17 cw(c5468.74,3861.28) 5455.94,3848.47
  MidLayer1 w4: v1@5435,3465.5 cw(c5435,3429.93) 5460.15,3455.08 ; v1@5435,3469.5 cw(c5435,3443.59) 5453.32,3461.91 ; v1@5435,3473.5 cw(c5435,3457.25) 5446.49,3468.74 ; v1(5435,3475) 5435,3476.55 5436.46,3478.01 5437.22,3478.01 5459.52,3455.71 5502.52,3455.71 5515.19,3468.37 5515.19,3498.31 5494,3519.5 5489.44,3519.5 5474.5,3534.44 5474.5,3591.81 5473.5,3592.81 5473.5,3628.29 5484.25,3639.04 5484.25,3660 5484.25,3670 5484.25,3718.62 5484.25,3812.16 ; v1@5444.5,3475 ccw(c5454.8,3475) 5447.52,3467.71 ; v3@5468.09,3828.2 cw(c5466.51,3810.16) 5480.38,3821.8 cw(c5494.25,3833.44) v3@5476.21,3835.02 ; 5480.13,3822.09 cw(c5470.2,3812.16) 5484.25,3812.16 ; 5484.25,3798.23 5484.25,3812.16
  MidLayer2 w4: v1(5435,3475) 5435,3476.55 5436.46,3478.01 5437.22,3478.01 5440.19,3475.04 5440.19,3473.37 5437.32,3470.5 5429.44,3470.5 5409.5,3450.56 5409.5,3409.5 5392.5,3392.5 5392.5,3329.36 5406.86,3315 5406.86,3243.71 5396.52,3233.37 5396.52,3185.37 5423.52,3158.37 5423.52,3020 5453.52,2990 5550.23,2990 v1(5598.52,2941.71) ; v1@5589.02,2941.71 ccw(c5566.09,2941.71) 5582.31,2957.93 ccw(c5598.52,2974.14) v1@5598.52,2951.21 ; v1@5593.02,2941.71 ccw(c5579.75,2941.71) 5589.14,2951.1 ccw(c5598.52,2960.49) v1@5598.52,2947.21
TFT_IO.DB2: J27.30 U8.AE12 | length 1752.5
  Top Layer w4: U8.AE12@5323.6,3737.24 cw(c5305.88,3737.24) 5318.41,3724.71 ; U8.AE12@5330.94,3729.9 ccw(c5330.94,3712.17) 5318.41,3724.71 ; v1@5373.28,3291.72 ccw(c5357.06,3307.93) 5380,3307.93 ccw(c5402.93,3307.93) v1@5386.72,3291.72 ; v1@5376.11,3288.89 ccw(c5366.72,3298.28) 5380,3298.28 ccw(c5393.28,3298.28) v1@5383.89,3288.89 ; v1@5381.86,3283.37 5380.23,3285 v1(5380,3285) 5380,3312.87 5390,3322.87 5390,3340.9 5340.19,3390.71 5340.19,3416.71 5331.86,3425.04 5325.86,3425.04 5309.19,3441.71 5309.19,3579 5315.19,3585 5315.44,3585.25 5315.44,3655.26 5315.44,3660 5315.44,3670 5315.44,3717.53 cw(c5325.59,3717.53) 5318.41,3724.71 ; v1(5470,2880) 5553.15,2880 5589.86,2916.71 5623.52,2916.71 5723.52,3016.71 5723.52,3033.37 5728.41,3033.37 J27.30@5728.41,3041.61 ; v1@5473.89,2876.11 cw(c5483.28,2866.72) 5483.28,2880 cw(c5483.28,2893.28) v1@5473.89,2883.89 ; v1@5476.72,2873.28 cw(c5492.93,2857.06) 5492.93,2880 cw(c5492.93,2902.93) v1@5476.72,2886.72 ; 5714.79,3007.97 cw(c5728.41,2994.35) J27.30@5728.41,3013.61 ; 5719.87,3013.06 ccw(c5713.44,3019.49) J27.30@5722.54,3019.49 ; J27.30@5721.62,3014.8 cw(c5728.41,3008) J27.30@5728.41,3017.61
  MidLayer2 w4: v1@5373.28,3278.28 cw(c5350.57,3255.57) 5382.69,3255.57 ; v1@5376.11,3281.11 cw(c5360.23,3265.23) 5382.69,3265.23 ; v1(5380,3285) 5382.69,3282.31 5382.69,3165 5348.52,3130.83 5348.52,3053.52 5281.02,2986.02 5281.02,2912.66 5319.48,2874.21 5464.21,2874.21 v1(5470,2880) ; 5382.69,3268.56 cw(c5396.44,3268.56) v1@5386.72,3278.28 ; 5433.08,2874.21 ccw(c5433.08,2916.92) v1@5463.28,2886.72 ; 5442.74,2874.21 ccw(c5442.74,2907.26) v1@5466.11,2883.89 ; 5452.4,2874.21 ccw(c5452.4,2897.6) v1@5468.94,2881.06
TFT_IO.DB3: J27.28 U8.AE15 | length 1621.6
  Top Layer w4: v1(5440.19,3502.71) 5464.52,3527.04 5464.52,3658.37 ; v1@5440.19,3508.21 ccw(c5440.19,3521.49) 5449.58,3512.1 ccw(c5458.97,3502.71) v1@5445.69,3502.71 ; v1@5440.19,3512.21 ccw(c5440.19,3535.14) 5456.41,3518.92 ccw(c5472.63,3502.71) v1@5449.69,3502.71 ; U8.AE15@5449.06,3729.9 cw(c5449.06,3712.17) 5461.59,3724.71 ; U8.AE15@5456.4,3737.24 ccw(c5474.12,3737.24) 5461.59,3724.71 ; v1@5740.81,2990.09 ccw(c5722.17,3008.72) 5748.52,3008.72 ; v1@5743.64,2987.26 ccw(c5731.83,2999.07) 5748.52,2999.07 ; v1(5747.52,2983.37) 5748.52,2984.37 5748.52,3011.15 5756.86,3019.48 ; 5748.52,3003.9 ccw(c5768.04,3003.9) v1@5754.24,2990.09 ; J27.28@5762.88,3016.24 ccw(c5756.86,3012.25) 5756.86,3019.48 ; J27.28@5762.88,3022.72 cw(c5756.86,3026.69) 5756.86,3019.48 ; J27.28@5767.78,3041.61 5767.78,3019.48 5756.86,3019.48 ; 5461.59,3724.71 cw(c5454.41,3717.53) 5464.56,3717.53 5464.56,3670 5464.56,3660 5464.56,3658.37 ; 5464.56,3658.37 5464.56,3655.26 5464.56,3658.37
  MidLayer1 w4: v1@5723.47,3251.66 cw(c5707.26,3235.44) 5730.19,3235.44 cw(c5753.13,3235.44) v1@5736.91,3251.66 ; v1@5726.3,3254.49 cw(c5716.91,3245.1) 5730.19,3245.1 cw(c5743.47,3245.1) v1@5734.08,3254.49 ; v1@5731.86,3256.71 v1(5730.19,3258.37) 5730.19,3000.71 5731.86,2999.04 ; 5731.86,2999.04 v1(5747.52,2983.37) 5731.86,2999.04
  Bottom Layer w4: 5403.01,3508.61 cw(c5403.01,3465.52) v1@5433.47,3495.99 ; 5412.66,3508.61 cw(c5412.66,3475.18) v1@5436.3,3498.82 ; 5422.32,3508.61 cw(c5422.32,3484.84) v1@5439.13,3501.65 ; v1(5440.19,3502.71) 5434.29,3508.61 5374.95,3508.61 5364.7,3498.36 5364.7,3483.86 5365.86,3482.71 5365.86,3475.04 5374.19,3466.71 5399.52,3466.71 5407.86,3458.37 5407.86,3415.71 5465.19,3358.37 5490.19,3358.37 5548.52,3300.04 5553.9,3300.04 5571.44,3282.5 5597.25,3282.5 5647.79,3333.04 5715.52,3333.04 5730.19,3318.37 v1(5730.19,3258.37) ; v1@5723.47,3265.09 ccw(c5707.26,3281.31) 5730.19,3281.31 ccw(c5753.13,3281.31) v1@5736.91,3265.09 ; v1@5726.3,3262.26 ccw(c5716.91,3271.65) 5730.19,3271.65 ccw(c5743.47,3271.65) v1@5734.08,3262.26
TFT_IO.DB4: J27.9 U8.AF23 | length 932.1
  Top Layer w4: U8.AF23@5758.71,3692.57 cw(c5745.91,3679.77) 5764.02,3679.77 cw(c5782.12,3679.77) U8.AF23@5769.32,3692.57 ; U8.AF23@5758.82,3692.68 cw(c5746.29,3680.15) 5764.02,3680.15 cw(c5781.74,3680.15) U8.AF23@5769.21,3692.68 ; U8.AF23@5764.02,3697.87 5764.02,3670 5764.02,3660 5764.02,3548.84 5799.28,3513.58 5813.97,3513.58 5831.45,3496.1 5856.86,3470.69 5856.86,3446.71 5878.52,3425.04 5988.52,3425.04 5990.19,3423.37 5990.19,3355.63 6029.11,3316.71 6090.19,3316.71 6140.19,3266.71 6140.19,3140.37 6141.79,3140.37 J27.9@6141.8,3118.39 ; J27.9@6137.64,3144.67 ccw(c6131.5,3150.81) 6140.19,3150.81 ; 6140.19,3148.92 ccw(c6150.2,3148.92) J27.9@6143.12,3141.84 ; 6140.19,3158.57 ccw(c6159.86,3158.57) J27.9@6145.95,3144.67
TFT_IO.DB5: J27.35 U8.AC15 | length 1299.4
  Top Layer w4: U8.AC15@5449.06,3808.48 cw(c5449.06,3790.38) 5461.86,3803.18 cw(c5474.66,3815.98) U8.AC15@5456.56,3815.98 ; U8.AC15@5449.06,3808.64 cw(c5449.06,3790.92) 5461.59,3803.45 cw(c5474.12,3815.98) U8.AC15@5456.4,3815.98 ; U8.AC15@5449.06,3815.98 v3(5468.74,3796.3) ; v1(5489.19,3166.71) 5505.86,3183.37 5535.48,3183.37 5535.65,3183.21 5600.69,3183.21 5608.86,3175.04 5608.86,3161.14 5629.99,3140.01 J27.35@5629.99,3118.39 ; v1@5489.19,3172.21 ccw(c5489.19,3185.49) 5498.58,3176.1 ccw(c5507.97,3166.71) v1@5494.69,3166.71 ; v1@5489.19,3176.21 ccw(c5489.19,3199.14) 5505.41,3182.93 ccw(c5521.63,3166.71) v1@5498.69,3166.71 ; 5619.11,3150.89 ccw(c5629.99,3161.77) J27.35@5629.99,3146.39 ; 5620.31,3149.69 cw(c5611.13,3140.51) J27.35@5624.11,3140.51 ; 5455.94,3809.1 cw(c5443.13,3796.3) 5461.24,3796.3 ccw(c5443.13,3796.3) 5455.94,3809.1 ; 5455.94,3809.1 ccw(c5468.74,3821.91) 5468.74,3803.8 cw(c5468.74,3821.91) 5455.94,3809.1
  MidLayer1 w4: v3@5463.44,3791 cw(c5450.63,3778.19) 5468.74,3778.19 cw(c5486.85,3778.19) v3@5474.04,3791 ; v3@5463.55,3791.11 cw(c5451.01,3778.57) 5468.74,3778.57 cw(c5486.47,3778.57) v3@5473.93,3791.11 ; v3(5468.74,3796.3) 5468.74,3670 5468.74,3660 5468.74,3634.85 5465.5,3631.61 5465.5,3589.5 5466.5,3588.5 5466.5,3518.8 v1(5483.3,3502) ; v1@5473.8,3502 ccw(c5450.86,3502) 5467.08,3518.22 ccw(c5483.3,3534.43) v1@5483.3,3511.5 ; v1@5477.8,3502 ccw(c5464.52,3502) 5473.91,3511.39 ccw(c5483.3,3520.78) v1@5483.3,3507.5
  MidLayer2 w4: v1@5482.47,3159.99 ccw(c5466.26,3143.77) 5466.26,3166.71 ccw(c5466.26,3189.64) v1@5482.47,3173.43 ; v1(5483.3,3502) 5496.88,3502 5516.02,3482.85 5516.02,3345.52 5485.19,3314.69 5485.19,3245.04 5455.86,3215.71 5455.86,3174.14 5463.29,3166.71 v1(5489.19,3166.71) ; v1@5485.3,3162.82 ccw(c5475.91,3153.43) 5475.91,3166.71 ccw(c5475.91,3179.99) v1@5485.3,3170.6
TFT_IO.DB6: J27.37 U8.AC14 | length 1697.7
  Top Layer w4: U8.AC14@5409.69,3808.48 cw(c5409.69,3790.38) 5422.49,3803.18 cw(c5435.29,3815.98) U8.AC14@5417.19,3815.98 ; U8.AC14@5409.69,3808.64 cw(c5409.69,3790.92) 5422.22,3803.45 cw(c5434.75,3815.98) U8.AC14@5417.03,3815.98 ; U8.AC14@5409.69,3815.98 v3(5429.37,3796.3) ; v1@5583.47,3157.99 cw(c5567.26,3141.77) 5590.19,3141.77 cw(c5613.13,3141.77) v1@5596.91,3157.99 ; v1@5586.3,3160.82 cw(c5576.91,3151.43) 5590.19,3151.43 cw(c5603.47,3151.43) v1@5594.08,3160.82 ; J27.37@5586.46,3144.67 ccw(c5577.46,3153.66) v1@5590.19,3153.66 ; v1@5590.19,3155.72 ccw(c5605.83,3155.72) J27.37@5594.77,3144.67 ; v1(5590.19,3164.71) 5590.19,3140.13 5590.62,3140.13 J27.37@5590.62,3118.39 ; 5416.57,3809.1 cw(c5403.76,3796.3) 5421.87,3796.3 ccw(c5403.76,3796.3) 5416.57,3809.1 ; 5416.57,3809.1 ccw(c5429.37,3821.91) 5429.37,3803.8 cw(c5429.37,3821.91) 5416.57,3809.1
  MidLayer1 w4: 5418.08,3563.82 cw(c5387.64,3533.37) v1@5430.69,3533.37 ; v3@5424.18,3791.11 cw(c5411.64,3778.57) 5429.37,3778.57 cw(c5447.1,3778.57) v3@5434.56,3791.11 ; 5424.91,3556.99 cw(c5401.29,3533.37) v1@5434.69,3533.37 ; v3(5429.37,3796.3) 5429.37,3718.62 5429.37,3670 5429.37,3660 5429.37,3655.26 5406.86,3632.75 5406.86,3575.04 5440.19,3541.71 v1(5440.19,3533.37) ; 5431.74,3550.16 cw(c5414.95,3533.37) v1@5438.69,3533.37 ; 5429.37,3778.19 cw(c5447.48,3778.19) 5434.67,3791 ccw(c5447.48,3778.19) 5429.37,3778.19 ; 5429.37,3778.19 ccw(c5411.26,3778.19) 5424.07,3791 cw(c5411.26,3778.19) 5429.37,3778.19
  MidLayer2 w4: v1@5415.47,3205.43 ccw(c5396.03,3224.86) 5423.52,3224.86 ; v1@5418.3,3202.6 ccw(c5405.69,3215.21) 5423.52,3215.21 ; v1(5422.19,3198.71) 5422.19,3207.04 5423.52,3208.37 5423.52,3250.04 v1(5448.52,3275.04) ; 5423.52,3218.42 ccw(c5441.9,3218.42) v1@5428.91,3205.43 ; v1@5439.02,3275.04 cw(c5416.09,3275.04) 5432.31,3258.82 cw(c5448.52,3242.61) v1@5448.52,3265.54 ; v1@5443.02,3275.04 cw(c5429.75,3275.04) 5439.14,3265.65 cw(c5448.52,3256.26) v1@5448.52,3269.54
  Bottom Layer w4: v1@5422.19,3189.21 cw(c5422.19,3166.27) 5438.41,3182.49 cw(c5454.63,3198.71) v1@5431.69,3198.71 ; v1@5422.19,3193.21 cw(c5422.19,3179.93) 5431.58,3189.32 cw(c5440.97,3198.71) v1@5427.69,3198.71 ; v1(5422.19,3198.71) 5471.86,3149.04 5498.52,3149.04 5514.19,3164.71 v1(5590.19,3164.71) ; v1@5433.47,3526.66 ccw(c5417.26,3510.44) 5417.26,3533.37 ccw(c5417.26,3556.31) v1@5433.47,3540.09 ; v1@5436.3,3529.49 ccw(c5426.91,3520.1) 5426.91,3533.37 ccw(c5426.91,3546.65) v1@5436.3,3537.26 ; v1@5439.02,3275.04 ccw(c5416.09,3275.04) 5432.31,3291.26 ccw(c5448.52,3307.48) v1@5448.52,3284.54 ; v1(5440.19,3533.37) 5382.86,3533.37 5357.86,3508.37 5357.86,3502.83 5356.7,3501.67 5356.7,3480.55 5357.86,3479.39 5357.86,3451.71 5430,3379.56 5430,3293.56 v1(5448.52,3275.04) ; v1@5443.02,3275.04 ccw(c5429.75,3275.04) 5439.14,3284.43 ccw(c5448.52,3293.82) v1@5448.52,3280.54 ; v1@5583.47,3157.99 ccw(c5567.26,3141.77) 5567.26,3164.71 ccw(c5567.26,3187.64) v1@5583.47,3171.43 ; v1@5586.3,3160.82 ccw(c5576.91,3151.43) 5576.91,3164.71 ccw(c5576.91,3177.99) v1@5586.3,3168.6
TFT_IO.DB7: J27.39 U8.AC12 | length 1486.9
  Top Layer w4: v3(5311.26,3796.3) U8.AC12@5330.94,3815.98 ; U8.AC12@5323.44,3815.98 cw(c5305.34,3815.98) 5318.14,3803.18 cw(c5330.94,3790.38) U8.AC12@5330.94,3808.48 ; U8.AC12@5323.6,3815.98 cw(c5305.88,3815.98) 5318.41,3803.45 cw(c5330.94,3790.92) U8.AC12@5330.94,3808.64 ; v1(5524.52,3116.71) 5549.57,3116.71 J27.39@5551.25,3118.39 ; v1@5528.41,3112.82 cw(c5537.8,3103.43) 5537.8,3116.71 cw(c5537.8,3129.99) v1@5528.41,3120.6 ; v1@5531.24,3109.99 cw(c5547.46,3093.77) 5547.46,3116.71 cw(c5547.46,3139.64) v1@5531.24,3123.43 ; v1@5533.01,3116.71 ccw(c5533.01,3136.62) J27.39@5547.09,3122.54 ; 5541.12,3116.71 cw(c5541.12,3108.26) J27.39@5547.09,3114.23 ; 5542.67,3116.71 ccw(c5542.67,3126.96) J27.39@5549.92,3119.71 ; 5324.06,3809.1 ccw(c5336.87,3796.3) 5318.76,3796.3 cw(c5336.87,3796.3) 5324.06,3809.1 ; 5324.06,3809.1 cw(c5311.26,3821.91) 5311.26,3803.8 ccw(c5311.26,3821.91) 5324.06,3809.1
  MidLayer1 w4: v1(5281.86,3308.37) 5298.52,3325.04 5298.52,3525.04 5311.26,3537.78 5311.26,3660 5311.26,3670 v3(5311.26,3796.3) ; v1@5281.86,3313.87 ccw(c5281.86,3327.15) 5291.25,3317.76 ccw(c5300.64,3308.37) v1@5287.36,3308.37 ; v1@5281.86,3317.87 ccw(c5281.86,3340.81) 5298.08,3324.59 ccw(c5314.29,3308.37) v1@5291.36,3308.37 ; v3@5305.96,3791 cw(c5293.15,3778.19) 5311.26,3778.19 cw(c5329.37,3778.19) v3@5316.56,3791 ; v3@5306.07,3791.11 cw(c5293.53,3778.57) 5311.26,3778.57 cw(c5328.99,3778.57) v3@5316.45,3791.11
  MidLayer2 w4: v1@5281.86,3298.87 cw(c5281.86,3275.94) 5298.07,3292.16 cw(c5314.29,3308.37) v1@5291.36,3308.37 ; v1@5281.86,3302.87 cw(c5281.86,3289.6) 5291.25,3298.99 cw(c5300.64,3308.37) v1@5287.36,3308.37 ; v1(5281.86,3308.37) 5306.19,3284.04 5306.19,3249.45 5299.52,3242.78 v1(5299.52,3183.37) ; v1@5292.81,3190.09 ccw(c5276.59,3206.31) 5299.52,3206.31 ccw(c5322.46,3206.31) v1@5306.24,3190.09 ; v1@5295.64,3187.26 ccw(c5286.25,3196.65) 5299.52,3196.65 ccw(c5312.8,3196.65) v1@5303.41,3187.26
  Bottom Layer w4: v1(5299.52,3183.37) 5348.52,3183.37 5373.52,3158.37 5398.52,3158.37 5440.19,3116.71 v1(5524.52,3116.71) ; v1@5303.41,3179.49 cw(c5312.8,3170.1) 5312.8,3183.37 cw(c5312.8,3196.65) v1@5303.41,3187.26 ; v1@5306.24,3176.66 cw(c5322.46,3160.44) 5322.46,3183.37 cw(c5322.46,3206.31) v1@5306.24,3190.09 ; v1@5517.81,3109.99 ccw(c5501.59,3093.77) 5501.59,3116.71 ccw(c5501.59,3139.64) v1@5517.81,3123.43 ; v1@5520.64,3112.82 ccw(c5511.25,3103.43) 5511.25,3116.71 ccw(c5511.25,3129.99) v1@5520.64,3120.6
TFT_IO.DB10: J27.11 U8.AC21 | length 1294.6
  Top Layer w4: U8.AC21@5685.28,3808.48 cw(c5685.28,3790.38) 5698.08,3803.18 cw(c5710.88,3815.98) U8.AC21@5692.78,3815.98 ; U8.AC21@5685.28,3808.64 cw(c5685.28,3790.92) 5697.81,3803.45 cw(c5710.34,3815.98) U8.AC21@5692.62,3815.98 ; U8.AC21@5685.28,3815.98 v3(5704.96,3796.3) ; v1@6091.81,3178.66 cw(c6055.47,3142.32) J27.11@6106.86,3142.32 ; v1@6094.64,3181.49 cw(c6065.13,3151.98) 6106.86,3151.98 ; v1@6097.46,3184.31 cw(c6074.79,3161.64) 6106.86,3161.64 ; J27.11@6098.27,3144.67 ccw(c6077.55,3165.39) 6106.86,3165.39 ; v1(6098.52,3185.37) 6106.86,3177.04 6106.86,3133.37 6102.43,3133.37 J27.11@6102.43,3118.39 ; v1@6100.29,3187.14 cw(c6084.44,3171.29) 6106.86,3171.29 ; J27.11@6101.1,3141.84 ccw(c6087.21,3155.73) 6106.86,3155.73 ; 5692.16,3809.1 cw(c5679.35,3796.3) 5697.46,3796.3 ccw(c5679.35,3796.3) 5692.16,3809.1 ; 5692.16,3809.1 ccw(c5704.96,3821.91) 5704.96,3803.8 cw(c5704.96,3821.91) 5692.16,3809.1
  MidLayer1 w4: v3@5699.77,3791.11 cw(c5687.23,3778.57) 5704.96,3778.57 cw(c5722.69,3778.57) v3@5710.15,3791.11 ; v3(5704.96,3796.3) 5704.96,3718.62 5704.96,3670 5704.96,3660 5704.96,3632.25 5748.52,3588.69 5748.52,3556.67 5780.15,3525.04 5872.17,3525.04 5872.21,3525 5931.86,3465.35 5931.86,3356 5990.19,3297.67 5990.19,3288.31 6061.79,3216.71 6081.86,3216.71 6098.52,3200.04 v1(6098.52,3185.37) ; 5704.96,3778.19 cw(c5723.07,3778.19) 5710.26,3791 ccw(c5723.07,3778.19) 5704.96,3778.19 ; 5704.96,3778.19 ccw(c5686.85,3778.19) 5699.66,3791 cw(c5686.85,3778.19) 5704.96,3778.19
TFT_IO.DB11: J27.13 U8.AD22 | length 1304
  Top Layer w4: v1@5910.02,3262.37 ccw(c5887.09,3262.37) 5903.31,3278.59 ccw(c5919.52,3294.81) v1@5919.52,3271.87 ; v1@5914.02,3262.37 ccw(c5900.75,3262.37) 5910.13,3271.76 ccw(c5919.52,3281.15) v1@5919.52,3267.87 ; v1(5919.52,3262.37) 5881.86,3300.04 5881.86,3325.04 5865.19,3341.71 5865.19,3423.37 5848.86,3439.71 5848.86,3467.37 5810.65,3505.58 5795.97,3505.58 5748.51,3553.04 5748.51,3567.72 5748.51,3595.18 5748.51,3660 5748.51,3670 5748.51,3736.73 ; J27.13@6063.06,3118.39 6063.06,3116.71 6071.86,3116.71 ; J27.13@6067.62,3114.69 cw(c6071.86,3111.26) 6071.86,3116.71 ; J27.13@6068.86,3119.28 ccw(c6071.86,3119.74) 6071.86,3116.71 ; 6084.75,3227.93 ccw(c6054.3,3258.37) v1@6097.36,3258.37 ; 6091.58,3234.76 ccw(c6067.96,3258.37) v1@6101.36,3258.37 ; 6098.4,3241.59 ccw(c6081.62,3258.37) v1@6105.36,3258.37 ; v1(6106.86,3258.37) 6106.86,3250.04 6073.52,3216.71 6073.52,3118.37 6071.86,3116.71 ; 5737.18,3764.08 cw(c5709.83,3736.73) 5748.51,3736.73 ; 5737.18,3764.08 cw(c5709.83,3736.73) 5748.51,3736.73 ; 5737.18,3764.08 cw(c5749.71,3776.61) 5731.99,3776.61 ccw(c5749.71,3776.61) 5737.18,3764.08 ; 5737.18,3764.08 ccw(c5724.65,3751.55) 5724.65,3769.27 cw(c5724.65,3751.55) 5737.18,3764.08
  Bottom Layer w4: v1@5919.52,3252.87 cw(c5919.52,3229.94) 5935.74,3246.16 cw(c5951.96,3262.37) v1@5929.02,3262.37 ; v1@5919.52,3256.87 cw(c5919.52,3243.6) 5928.91,3252.99 cw(c5938.3,3262.37) v1@5925.02,3262.37 ; v1(5919.52,3262.37) 5938.9,3243 6023,3243 6046.71,3266.71 6075,3266.71 6083.33,3258.37 v1(6106.86,3258.37) ; v1@6100.14,3251.66 ccw(c6083.92,3235.44) 6083.92,3258.37 ccw(c6083.92,3281.31) v1@6100.14,3265.09 ; v1@6102.97,3254.49 ccw(c6093.58,3245.1) 6093.58,3258.37 ccw(c6093.58,3271.65) v1@6102.97,3262.26
TFT_IO.DB12: J27.15 U8.AC19 | length 1589.6
  Top Layer w4: U8.AC19@5606.54,3808.48 cw(c5606.54,3790.38) 5619.34,3803.18 cw(c5632.14,3815.98) U8.AC19@5614.04,3815.98 ; U8.AC19@5606.54,3808.64 cw(c5606.54,3790.92) 5619.07,3803.45 cw(c5631.6,3815.98) U8.AC19@5613.88,3815.98 ; U8.AC19@5606.54,3815.98 v3(5626.22,3796.3) ; J27.15@6021.05,3145.76 ccw(c6018.89,3150.04) 6023.68,3150.04 ; J27.15@6021.56,3140.51 cw(c6039.02,3140.51) 6026.68,3152.86 ; J27.15@6023.69,3118.39 6023.68,3140.51 6023.68,3150.04 ; J27.15@6025.56,3140.51 cw(c6052.68,3140.51) 6033.5,3159.69 ; J27.15@6026.32,3145.76 cw(c6028.47,3150.04) 6023.68,3150.04 ; 6027.52,3153.7 ccw(c6006.18,3175.04) v1@6036.36,3175.04 ; J27.15@6029.56,3140.51 cw(c6066.34,3140.51) v1@6040.33,3166.52 ; 6034.35,3160.53 ccw(c6019.84,3175.04) v1@6040.36,3175.04 ; 6034.76,3160.94 cw(c6045.86,3149.85) v1@6045.86,3165.54 ; v1(6045.86,3175.04) 6045.86,3172.04 6023.86,3150.04 6023.68,3150.04 ; 5613.42,3809.1 cw(c5600.61,3796.3) 5618.72,3796.3 ccw(c5600.61,3796.3) 5613.42,3809.1 ; 5613.42,3809.1 ccw(c5626.22,3821.91) 5626.22,3803.8 cw(c5626.22,3821.91) 5613.42,3809.1
  MidLayer1 w4: v3@5620.92,3791 cw(c5608.11,3778.19) 5626.22,3778.19 cw(c5644.33,3778.19) v3@5631.52,3791 ; v3@5621.03,3791.11 cw(c5608.49,3778.57) 5626.22,3778.57 cw(c5643.95,3778.57) v3@5631.41,3791.11 ; v3(5626.22,3796.3) 5626.22,3718.62 5626.22,3670 5626.22,3660 5626.22,3641.41 5633.52,3634.1 5633.52,3540.04 5626.86,3533.37 5626.86,3510.71 5645.86,3491.71 ; v1@5657.67,3485.9 ccw(c5645.86,3476.79) 5645.86,3491.71 ; v1@5657.67,3497.51 cw(c5645.86,3506.63) 5645.86,3491.71 ; v1(5665.19,3491.71) 5645.86,3491.71
  MidLayer2 w4: 5646.13,3474.31 cw(c5665.19,3455.25) v1@5665.19,3482.21 ; 5650.15,3478.33 ccw(c5636.78,3491.71) v1@5655.69,3491.71 ; 5652.96,3481.14 cw(c5665.19,3468.91) v1@5665.19,3486.21 ; v1(5665.19,3491.71) 5663.52,3491.71 5640.19,3468.37 5640.19,3347.06 5627.5,3334.37 5627.5,3295.06 5639.19,3283.37 5666.19,3283.37 5716.19,3233.37 5795.19,3233.37 5819.86,3208.71 5944.52,3208.71 5961.52,3191.71 5961.52,3158.37 5978.19,3141.71 6012.52,3141.71 v1(6045.86,3175.04) ; v1@6036.36,3175.04 cw(c6013.42,3175.04) 6029.64,3158.82 cw(c6045.86,3142.61) v1@6045.86,3165.54 ; v1@6040.36,3175.04 cw(c6027.08,3175.04) 6036.47,3165.65 cw(c6045.86,3156.26) v1@6045.86,3169.54
TFT_IO.DB13: J27.17 U8.Y17 | length 1498.5
  Top Layer w4: U8.Y17@5527.8,3926.59 cw(c5527.8,3908.49) 5540.6,3921.29 cw(c5553.4,3934.09) U8.Y17@5535.3,3934.09 ; U8.Y17@5527.8,3926.75 cw(c5527.8,3909.03) 5540.33,3921.56 cw(c5552.86,3934.09) U8.Y17@5535.14,3934.09 ; U8.Y17@5527.8,3934.09 v3(5547.48,3914.41) ; v1@5973.47,3158.32 cw(c5953.23,3138.08) J27.17@5981.86,3138.08 ; v1@5976.3,3161.15 cw(c5962.89,3147.74) J27.17@5981.86,3147.74 ; J27.17@5980.16,3144.67 ccw(c5976.07,3148.75) 5981.86,3148.75 ; v1(5980.19,3165.04) 5981.86,3163.37 5981.86,3125.04 5984.32,3125.04 J27.17@5984.32,3118.39 ; J27.17@5981.86,3146.13 cw(c5999.1,3146.13) v1@5986.91,3158.32 ; 5981.86,3150.97 ccw(c5994.78,3150.97) J27.17@5985.64,3141.84 ; v1@5981.86,3160.63 ccw(c6004.44,3160.63) J27.17@5988.47,3144.67 ; 5534.68,3927.21 cw(c5521.87,3914.41) 5539.98,3914.41 ccw(c5521.87,3914.41) 5534.68,3927.21 ; 5534.68,3927.21 ccw(c5547.48,3940.02) 5547.48,3921.91 cw(c5547.48,3940.02) 5534.68,3927.21
  MidLayer2 w4: v3@5546.83,3906.94 cw(c5545.25,3888.9) 5559.12,3900.54 cw(c5572.99,3912.18) v3@5554.95,3913.76 ; 5558.87,3900.83 cw(c5548.94,3890.9) 5562.99,3890.9 ; 5562.99,3680.84 5562.99,3685 ; 5562.99,3876.97 5562.99,3890.9 ; v1(5980.19,3165.04) 6005,3189.85 6005,3229.56 5998.52,3236.04 5920.86,3236.04 5898.52,3258.37 5758.86,3258.37 5739.52,3277.71 5688.86,3277.71 5664.19,3302.38 5664.19,3401.35 5691.19,3428.35 5691.19,3463.37 5691.19,3471.73 5682.86,3480.06 5682.86,3526.71 5609.52,3600.04 5590.19,3600.04 5573.52,3616.71 5573.52,3622 5562.99,3632.54 5562.99,3660 5562.99,3670 5562.99,3685 ; v1@5980.19,3170.54 ccw(c5980.19,3183.82) 5989.58,3174.43 ccw(c5998.97,3165.04) v1@5985.69,3165.04 ; v1@5980.19,3174.54 ccw(c5980.19,3197.48) 5996.41,3181.26 ccw(c6012.63,3165.04) v1@5989.69,3165.04 ; 5562.99,3685 5562.99,3797.36 5562.99,3890.9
